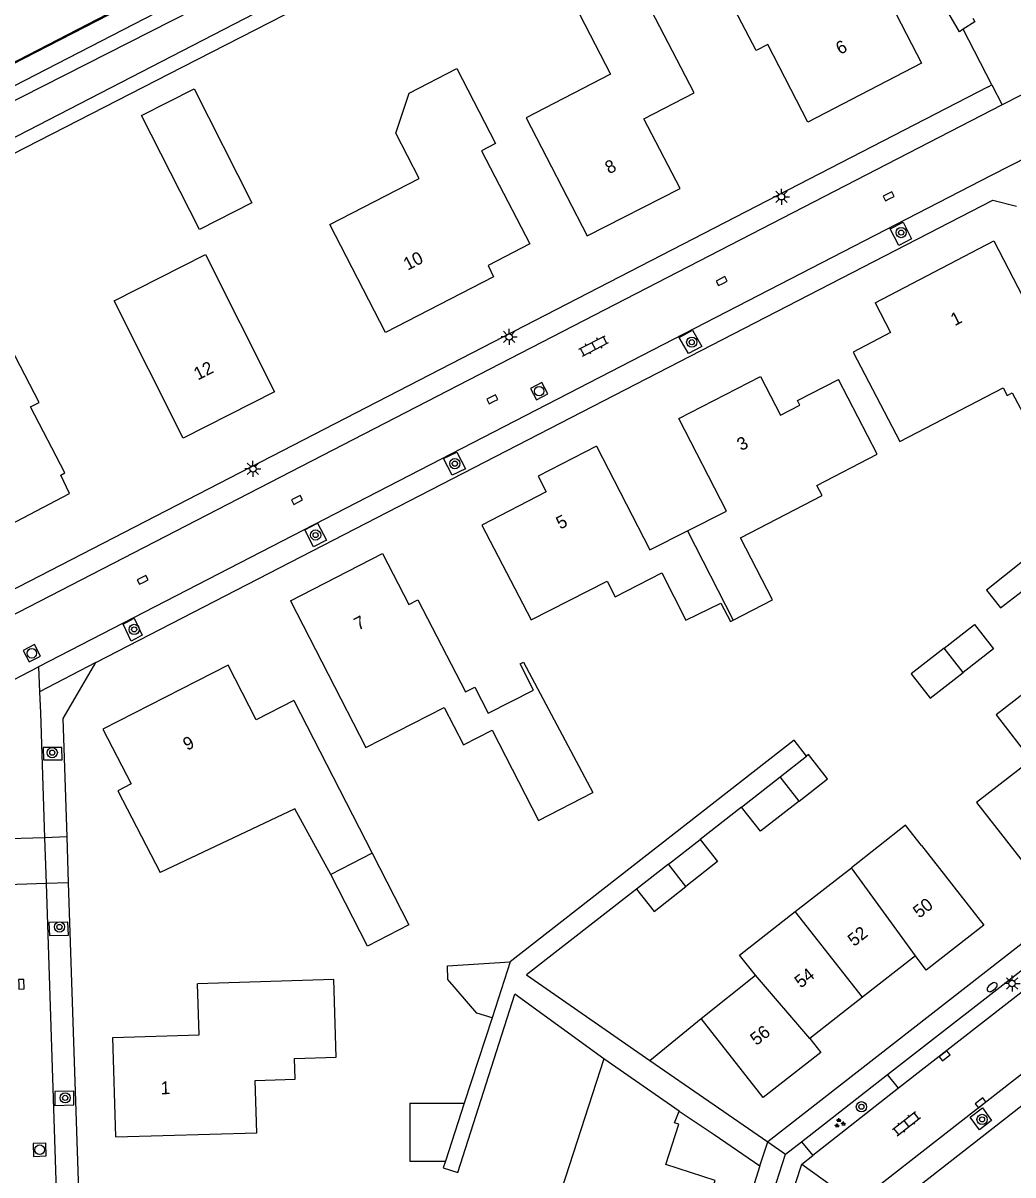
# Model space of a CAD drawing. Extents: x 136000 to 141014, y 402000 to 403500.
# Drawn here: x 137119.1 to 137196.5, y 402168.2 to 402258.2 of the extents above; entities that cross this region are included whole.
import ezdxf

# ---------------------------------------------------------------- set-up
doc = ezdxf.new("R2010")
doc.units = 0
for name, color, linetype in [('gg-afsc-erfafscheiding', 7, 'Continuous'), ('gg-anno-huisnummerreeks BGT', 7, 'Continuous'), ('gg-bbg-bijgebouw', 7, 'Continuous'), ('gg-bbg-gedigitaliseerde bebouwing', 7, 'Continuous'), ('gg-bbg-gedigitaliseerde bijgebouw', 7, 'Continuous'), ('gg-bbg-hoofdgebouw', 7, 'Continuous'), ('gg-bbg-luifel en loopbrug', 7, 'Continuous'), ('gg-bbg-tussenscheiding', 7, 'Continuous'), ('gg-knt-verharding', 7, 'Continuous'), ('gg-knt-verharding nz', 7, 'Continuous'), ('gg-kntw-bovenkant insteek waterloop', 7, 'Continuous'), ('gg-kntw-waterlijn', 7, 'Continuous'), ('gt-grn-groengrens', 7, 'Continuous'), ('gt-grn-weggrens', 7, 'Continuous'), ('gt-symb-boom', 7, 'Continuous'), ('gt-symb-brandkraan', 7, 'Continuous'), ('gt-symb-groenvak', 7, 'Continuous'), ('gt-symb-klinker verharding', 7, 'Continuous'), ('gt-symb-kolk', 7, 'Continuous'), ('gt-symb-lichtmast', 7, 'Continuous'), ('gt-symb-rioolschacht', 7, 'Continuous')]:
    doc.layers.add(name, color=color, linetype=linetype)

# ---------------------------------------------------------------- blocks, each defined once
blk = doc.blocks.new('gt0-KOLK')
at = {"layer": 'gt-symb-kolk'}
blk.add_lwpolyline([(0, 0), (0.375, 0), (0.375, 0.4), (-0.375, 0.4), (-0.375, 0), (0, 0)], dxfattribs=at)
blk = doc.blocks.new('gt0-GRVAK')
at = {"layer": 'gt-symb-groenvak'}
for p, q in [((-0.11, 0.189), (-0.228, 0.24)), ((-0.182, 0.153), (0.088, 0.153)), ((-0.091, 0.211), (-0.156, 0.322)), ((-0.047, 0.214), (-0.047, 0.393)), ((-0.004, 0.211), (0.061, 0.322)), ((0.015, 0.189), (0.133, 0.24)), ((0.262, -0.052), (0.197, 0.059)), ((0.305, -0.049), (0.305, 0.13)), ((0.349, -0.052), (0.414, 0.059)), ((-0.245, -0.228), (-0.363, -0.177)), ((-0.318, -0.264), (-0.047, -0.264)), ((-0.226, -0.206), (-0.291, -0.095)), ((-0.183, -0.203), (-0.183, -0.024)), ((-0.139, -0.206), (-0.074, -0.095)), ((-0.12, -0.228), (-0.002, -0.177)), ((0.243, -0.074), (0.125, -0.023)), ((0.17, -0.11), (0.441, -0.11)), ((0.368, -0.074), (0.486, -0.023))]:
    blk.add_line(p, q, dxfattribs=at)
blk = doc.blocks.new('gt0-BOOM')
at = {"layer": 'gt-symb-boom'}
for radius in [0.4, 0.2]:
    blk.add_circle((0, 0), radius, dxfattribs=at)
blk = doc.blocks.new('gt0-KL1')
at = {"layer": 'gt-symb-klinker verharding'}
for p, q in [((-1.15, 0.3), (1.15, 0.3)), ((-1, -0.3), (-1, 0.3)), ((-0.5, 0.3), (-0.5, 0.45)), ((0, -0.3), (0, 0.3)), ((0.5, 0.3), (0.5, 0.45)), ((1, -0.3), (1, 0.3)), ((-1.15, -0.3), (1.15, -0.3)), ((-0.5, -0.45), (-0.5, -0.3)), ((0.5, -0.45), (0.5, -0.3))]:
    blk.add_line(p, q, dxfattribs=at)
blk = doc.blocks.new('gt0-RS')
at = {"layer": 'gt-symb-rioolschacht'}
blk.add_lwpolyline([(-0.5, -0.5), (0.5, -0.5), (0.5, 0.5), (-0.5, 0.5)], close=True, dxfattribs=at)
blk.add_circle((0, 0), 0.375, dxfattribs=at)
blk = doc.blocks.new('gt0-LMAST')
at = {"layer": 'gt-symb-lichtmast'}
for p, q in [((-0.182, 0.173), (-0.447, 0.438)), ((-0.005, 0.246), (-0.005, 0.621)), ((0.172, 0.173), (0.437, 0.438)), ((-0.255, -0.004), (-0.63, -0.004)), ((-0.182, -0.181), (-0.447, -0.446)), ((-0.005, -0.254), (-0.005, -0.629)), ((0.437, -0.446), (0.172, -0.181)), ((0.245, -0.004), (0.62, -0.004))]:
    blk.add_line(p, q, dxfattribs=at)
blk.add_circle((-0.005, -0.004), 0.25, dxfattribs=at)
blk = doc.blocks.new('gt0-BR')
at = {"layer": 'gt-symb-brandkraan'}
for centre, radius, start, end in [((-0.244, 0), 0.206, 107.56694, 252.43307), ((0.599, -2.664), 3, 106.89205, 107.56694), ((0, -0.691), 0.938, 73.10799, 106.89205), ((-0.599, -2.664), 3, 72.43309, 73.10799), ((0.244, 0), 0.206, 287.56695, 72.43309), ((0.599, 2.664), 3, 252.43307, 253.10797), ((0, 0.691), 0.938, 253.10797, 286.89206), ((-0.599, 2.664), 3, 286.89206, 287.56695)]:
    blk.add_arc(centre, radius, start, end, dxfattribs=at)

msp = doc.modelspace()

# ---------------------------------------------------------------- linework, layer by layer
at = {"layer": 'gg-afsc-erfafscheiding'}
for p, q in [((137175.234, 402196.94), (137172.002, 402194.407)), ((137167.044, 402190.519), (137158.43, 402183.829)), ((137164.488, 402177.271), (137157.513, 402182.314)), ((137155.736, 402180.477), (137153.567, 402173.803)), ((137170.359, 402173.163), (137173.11, 402171.353))]:
    msp.add_line(p, q, dxfattribs=at)
for points in [[(137199.886, 402218.262), (137194.388, 402213.883), (137195.486, 402212.505), (137197.512, 402214.076)], [(137180.315, 402200.923), (137179.352, 402202.157), (137157.152, 402184.834)], [(137152.095, 402169.273), (137151.921, 402168.739), (137153.06, 402168.377), (137157.513, 402182.314)]]:
    msp.add_lwpolyline(points, dxfattribs=at)
at = {"layer": 'gg-bbg-bijgebouw'}
msp.add_lwpolyline([(137136.968, 402244.176), (137132.871, 402242.091), (137128.341, 402250.998), (137132.441, 402253.076), (137136.968, 402244.176)], dxfattribs=at)
at = {"layer": 'gg-bbg-gedigitaliseerde bebouwing'}
for p, q in [((137158.203, 402208.277), (137163.629, 402198.086)), ((137140.233, 402205.264), (137146.354, 402193.338)), ((137189.315, 402193.934), (137194.171, 402187.713)), ((137146.354, 402193.338), (137143.126, 402191.68)), ((137179.447, 402188.765), (137183.832, 402192.19)), ((137172.09, 402180.417), (137176.322, 402183.79)), ((137164.488, 402177.271), (137160.806, 402165.918))]:
    msp.add_line(p, q, dxfattribs=at)
for points in [[(137174.586, 402211.544), (137177.666, 402213.141), (137175.164, 402217.97), (137181.549, 402221.279), (137181.134, 402222.083), (137185.844, 402224.522), (137182.815, 402230.358)], [(137187.607, 402225.505), (137195.685, 402229.712), (137196.007, 402229.1), (137196.398, 402229.306), (137197.821, 402226.62), (137202.308, 402228.986)], [(137154.937, 402218.974), (137158.788, 402211.561), (137164.729, 402214.607), (137165.36, 402213.377), (137169.002, 402215.245)], [(137169.002, 402215.245), (137170.9, 402211.538), (137173.632, 402212.873)], [(137139.976, 402213.055), (137145.883, 402201.582), (137152.007, 402204.729), (137153.511, 402201.8), (137155.751, 402202.95), (137159.381, 402195.897), (137163.629, 402198.086)], [(137173.632, 402212.873), (137174.377, 402211.436), (137174.586, 402211.544)], [(137200.999, 402205.628), (137199.514, 402207.54), (137195.138, 402204.141), (137197.875, 402200.617)], [(137197.875, 402200.617), (137193.617, 402197.291), (137198.479, 402191.07)], [(137143.126, 402191.68), (137140.323, 402196.792), (137129.787, 402191.817)], [(137189.315, 402193.934), (137188.067, 402195.521), (137183.832, 402192.19)], [(137176.322, 402183.79), (137175.09, 402185.363), (137179.447, 402188.765)], [(137140.295, 402177.293), (137143.546, 402177.392), (137143.361, 402183.455), (137132.71, 402183.13)], [(137126.34, 402171.153), (137137.353, 402171.465), (137137.231, 402175.568), (137140.343, 402175.661), (137140.295, 402177.293)]]:
    msp.add_lwpolyline(points, dxfattribs=at)
at = {"layer": 'gg-bbg-gedigitaliseerde bijgebouw'}
for p, q in [((137178.25, 402199.304), (137180.315, 402200.923)), ((137175.234, 402196.94), (137178.25, 402199.304)), ((137169.523, 402192.463), (137172.002, 402194.407)), ((137169.523, 402192.463), (137167.044, 402190.519)), ((137149.3, 402173.803), (137153.567, 402173.803)), ((137153.567, 402173.803), (137152.095, 402169.273))]:
    msp.add_line(p, q, dxfattribs=at)
for points in [[(137191.077, 402209.359), (137193.448, 402211.2), (137194.928, 402209.296), (137192.557, 402207.454)], [(137191.077, 402209.359), (137188.507, 402207.362), (137189.986, 402205.458), (137192.557, 402207.454)], [(137179.736, 402197.408), (137181.953, 402199.146), (137180.467, 402201.042), (137180.315, 402200.923)], [(137179.736, 402197.408), (137176.721, 402195.044), (137175.234, 402196.94)], [(137172.002, 402194.407), (137173.359, 402192.675), (137170.88, 402190.732)], [(137167.044, 402190.519), (137168.401, 402188.788), (137170.88, 402190.732)], [(137149.3, 402173.803), (137149.3, 402169.273), (137152.095, 402169.273)]]:
    msp.add_lwpolyline(points, dxfattribs=at)
at = {"layer": 'gg-bbg-hoofdgebouw'}
for p, q in [((137188.829, 402185.307), (137184.696, 402182.069)), ((137184.696, 402182.069), (137180.57, 402178.837)), ((137176.941, 402174.233), (137172.09, 402180.417)), ((137170.359, 402173.163), (137164.488, 402177.271))]:
    msp.add_line(p, q, dxfattribs=at)
for points in [[(137189.655, 402262.053), (137186.547, 402260.445), (137189.322, 402255.08), (137180.42, 402250.476), (137177.297, 402256.539), (137176.374, 402256.075), (137174.442, 402259.81), (137178.182, 402261.759), (137178.665, 402260.826)], [(137163.17, 402241.585), (137170.433, 402245.286), (137167.607, 402250.721), (137171.543, 402252.763), (137167.168, 402261.215), (137162.607, 402258.856), (137165.001, 402254.226), (137158.406, 402250.817), (137163.17, 402241.585)], [(137147.417, 402234.028), (137143.058, 402242.473), (137150.05, 402246.079), (137148.226, 402249.614), (137149.257, 402252.747), (137152.988, 402254.662), (137156, 402248.794), (137154.923, 402248.24), (137158.703, 402240.958), (137155.424, 402239.257), (137155.865, 402238.386), (137147.417, 402234.028)], [(137185.68, 402236.339), (137194.96, 402241.184), (137198.35, 402234.646), (137199.151, 402235.051), (137202.308, 402228.986)], [(137138.729, 402229.381), (137131.591, 402225.774), (137126.187, 402236.504), (137133.332, 402240.117), (137138.729, 402229.381)], [(137110.555, 402216.953), (137113.619, 402218.514), (137113.894, 402217.965), (137114.839, 402218.482), (137114.601, 402219.035), (137116.234, 402219.865), (137116.975, 402218.457), (137122.707, 402221.442), (137122.022, 402222.876), (137122.345, 402223.064), (137119.662, 402228.217), (137120.324, 402228.557), (137115.128, 402238.562), (137108.516, 402235.127), (137111.46, 402229.516), (137110.614, 402226.66), (137106.597, 402224.573), (137110.555, 402216.953)], [(137185.68, 402236.339), (137186.89, 402234.031), (137183.963, 402232.496), (137187.607, 402225.505)], [(137170.345, 402227.301), (137176.731, 402230.6), (137178.296, 402227.571), (137179.806, 402228.351), (137179.629, 402228.704), (137182.815, 402230.358)], [(137171.013, 402218.53), (137174.075, 402220.064), (137170.345, 402227.301)], [(137163.912, 402225.143), (137159.352, 402222.794), (137159.962, 402221.585), (137154.937, 402218.974)], [(137163.912, 402225.143), (137168.075, 402217.057), (137171.013, 402218.53)], [(137139.976, 402213.055), (137147.172, 402216.762), (137149.229, 402212.771), (137149.94, 402213.137)], [(137149.94, 402213.137), (137153.658, 402205.94), (137154.385, 402206.313), (137155.431, 402204.276), (137158.97, 402206.085), (137157.925, 402208.129), (137158.203, 402208.277)], [(137140.233, 402205.264), (137137.286, 402203.756), (137135.109, 402208.023), (137125.321, 402203.015), (137127.523, 402198.752), (137126.488, 402198.21), (137129.787, 402191.817)], [(137194.171, 402187.713), (137189.683, 402184.183), (137188.829, 402185.307)], [(137126.34, 402171.153), (137126.096, 402178.922), (137132.835, 402179.134), (137132.71, 402183.13)], [(137180.57, 402178.837), (137181.436, 402177.746), (137176.941, 402174.233)], [(137169.337, 402169.007), (137170.351, 402172.153), (137169.999, 402172.266), (137170.359, 402173.163)], [(137171.466, 402162.46), (137173.184, 402167.76), (137169.337, 402169.007)]]:
    msp.add_lwpolyline(points, dxfattribs=at)
at = {"layer": 'gg-bbg-luifel en loopbrug'}
msp.add_line((137157.152, 402184.834), (137155.736, 402180.477), dxfattribs=at)
for points in [[(137146.354, 402193.338), (137149.234, 402187.727), (137146.006, 402186.07), (137143.126, 402191.68)], [(137155.736, 402180.477), (137154.541, 402180.819), (137152.274, 402183.462), (137152.247, 402184.541), (137157.152, 402184.834)]]:
    msp.add_lwpolyline(points, dxfattribs=at)
at = {"layer": 'gg-bbg-tussenscheiding'}
for p, q in [((137171.013, 402218.53), (137174.586, 402211.544)), ((137192.557, 402207.454), (137191.077, 402209.359)), ((137179.736, 402197.408), (137178.25, 402199.304)), ((137170.88, 402190.732), (137169.523, 402192.463)), ((137188.829, 402185.307), (137183.832, 402192.19)), ((137184.696, 402182.069), (137179.447, 402188.765)), ((137180.57, 402178.837), (137176.322, 402183.79))]:
    msp.add_line(p, q, dxfattribs=at)
at = {"layer": 'gg-knt-verharding'}
for p, q in [((137192.27, 402257.54), (137189.655, 402262.053)), ((137194.817, 402253.388), (137192.576, 402257.734)), ((137194.511, 402253.23), (137112.718, 402211.057)), ((137194.511, 402253.23), (137194.817, 402253.388)), ((137219.657, 402203.828), (137177.285, 402170.761)), ((137186.663, 402176.03), (137216.386, 402199.194)), ((137120.761, 402194.542), (137116.255, 402194.394)), ((137122.515, 402194.6), (137120.761, 402194.542)), ((137122.633, 402191.022), (137122.515, 402194.6)), ((137120.879, 402190.964), (137116.373, 402190.816)), ((137122.633, 402191.022), (137120.879, 402190.964)), ((137124.321, 402139.859), (137122.633, 402191.022)), ((137158.43, 402183.829), (137168.078, 402177.141)), ((137168.078, 402177.141), (137172.09, 402180.417)), ((137168.078, 402177.141), (137177.285, 402170.761)), ((137179.917, 402170.782), (137186.663, 402176.03)), ((137187.506, 402174.961), (137186.663, 402176.03)), ((137187.506, 402174.961), (137180.809, 402169.696)), ((137173.11, 402171.353), (137176.678, 402168.885)), ((137178.678, 402169.818), (137179.917, 402170.782)), ((137179.917, 402170.782), (137180.809, 402169.696)), ((137173.776, 402154.537), (137178.678, 402169.818)), ((137176.678, 402168.885), (137161.685, 402122.523))]:
    msp.add_line(p, q, dxfattribs=at)
for points in [[(137114.039, 402252.931), (137136.533, 402264.565), (137178.437, 402286.603), (137198.547, 402296.864)], [(137193.315, 402258.609), (137193.487, 402258.314), (137192.576, 402257.734)], [(137124.757, 402208.239), (137194.898, 402244.385), (137196.728, 402243.905)], [(137186.868, 402242.141), (137187.865, 402242.657), (137188.526, 402241.349), (137187.529, 402240.833), (137186.868, 402242.141)], [(137170.376, 402233.651), (137171.405, 402234.204), (137172.129, 402232.934), (137171.1, 402232.381), (137170.376, 402233.651)], [(137151.944, 402224.19), (137152.974, 402224.684), (137153.659, 402223.366), (137152.63, 402222.872), (137151.944, 402224.19)], [(137141.098, 402218.601), (137142.102, 402219.12), (137142.789, 402217.797), (137141.785, 402217.278), (137141.098, 402218.601)], [(137126.905, 402211.228), (137127.773, 402211.691), (137128.388, 402210.367), (137127.52, 402209.904), (137126.905, 402211.228)], [(137122.515, 402194.6), (137122.209, 402203.872), (137124.757, 402208.239)], [(137120.635, 402201.587), (137120.665, 402200.62), (137122.131, 402200.636), (137122.101, 402201.603), (137120.635, 402201.587)], [(137218.597, 402190.349), (137189.049, 402167.254), (137186.912, 402164.258)], [(137121.082, 402187.911), (137121.13, 402186.888), (137122.628, 402186.924), (137122.579, 402187.947), (137121.082, 402187.911)], [(137121.553, 402174.709), (137121.563, 402173.625), (137123.045, 402173.654), (137123.035, 402174.738), (137121.553, 402174.709)], [(137193.125, 402172.714), (137194.072, 402173.437), (137194.792, 402172.432), (137193.845, 402171.708), (137193.125, 402172.714)]]:
    msp.add_lwpolyline(points, dxfattribs=at)
at = {"layer": 'gg-knt-verharding nz'}
for p, q in [((137199.183, 402253.649), (137195.628, 402251.816)), ((137195.628, 402251.816), (137113.624, 402209.527)), ((137120.282, 402207.889), (137120.367, 402205.951)), ((137217.227, 402198.134), (137187.506, 402174.961)), ((137225.226, 402198.005), (137184.223, 402165.979)), ((137120.761, 402194.542), (137120.879, 402190.964)), ((137120.879, 402190.964), (137122.81, 402132.398)), ((137179.953, 402169.024), (137180.809, 402169.696)), ((137175.077, 402154.14), (137179.953, 402169.024))]:
    msp.add_line(p, q, dxfattribs=at)
for points in [[(137197.733, 402247.823), (137194.744, 402246.314), (137120.282, 402207.889)], [(137120.367, 402205.951), (137120.439, 402204.3), (137120.761, 402194.542)]]:
    msp.add_lwpolyline(points, dxfattribs=at)
at = {"layer": 'gg-kntw-bovenkant insteek waterloop'}
msp.add_line((137046.682, 402212.26), (137179.816, 402280.985), dxfattribs=at)
msp.add_lwpolyline([(137044.528, 402217.609), (137110.163, 402251.03), (137112.495, 402252.06), (137194.09, 402293.977)], dxfattribs=at)
at = {"layer": 'gg-kntw-waterlijn'}
msp.add_lwpolyline([(137043.484, 402206.955), (137042.996, 402210.257), (137043.425, 402211.894), (137044.284, 402213.469), (137046.308, 402215.065), (137065.655, 402225.358), (137078.207, 402231.684), (137102.163, 402243.942), (137139.102, 402262.696), (137173.81, 402280.459), (137194.975, 402291.136), (137194.445, 402292.358), (137162.599, 402276.104), (137107.252, 402247.583), (137063.182, 402225.333), (137045.277, 402215.852), (137043.437, 402214.4), (137042.367, 402212.642), (137041.807, 402211.297), (137041.833, 402208.678), (137041.99, 402206.763)], dxfattribs=at)
at = {"layer": 'gt-grn-groengrens'}
msp.add_line((137192.576, 402257.734), (137192.27, 402257.54), dxfattribs=at)
msp.add_lwpolyline([(137049.629, 402172.09), (137049.013, 402172.486), (137046.817, 402196.934), (137045.881, 402208.692), (137046.778, 402211.327), (137131.556, 402254.798), (137164.49, 402271.663), (137180.412, 402279.845)], dxfattribs=at)
at = {"layer": 'gt-grn-weggrens'}
for p, q in [((137194.817, 402253.388), (137195.628, 402251.816)), ((137124.757, 402208.239), (137120.367, 402205.951)), ((137112.958, 402204.103), (137120.282, 402207.889)), ((137176.678, 402168.885), (137177.285, 402170.761)), ((137177.285, 402170.761), (137178.678, 402169.818)), ((137179.953, 402169.024), (137184.223, 402165.979))]:
    msp.add_line(p, q, dxfattribs=at)

# ---------------------------------------------------------------- block references
at = {"layer": 'gt-symb-boom'}
for p in [(137187.722, 402241.839), (137171.349, 402233.272), (137152.832, 402223.78), (137141.947, 402218.2), (137127.76, 402210.825), (137121.357, 402201.191), (137121.922, 402187.566), (137122.37, 402174.21), (137184.613, 402173.514), (137194.047, 402172.525)]:
    msp.add_blockref('gt0-BOOM', p, dxfattribs=at)
at = {"layer": 'gt-symb-brandkraan', "rotation": 38.17653760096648}
msp.add_blockref('gt0-BR', (137194.831, 402182.863), dxfattribs=at)
at = {"layer": 'gt-symb-groenvak'}
msp.add_blockref('gt0-GRVAK', (137182.906, 402172.223), dxfattribs=at)
at = {"layer": 'gt-symb-klinker verharding'}
for p, rotation in [((137163.687, 402232.984), 27.307780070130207), ((137188.131, 402172.197), 38.01566048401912)]:
    msp.add_blockref('gt0-KL1', p, dxfattribs=dict(at, rotation=rotation))
at = {"layer": 'gt-symb-kolk'}
for p, rotation in [((137186.84, 402244.5), 27.256871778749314), ((137173.78, 402237.871), 27.256871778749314), ((137155.849, 402228.625), 27.256871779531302), ((137140.582, 402220.772), 27.256871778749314), ((137128.523, 402214.522), 27.256871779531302), ((137118.741, 402183.085), -88.22439947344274), ((137191.245, 402177.337), 38.01566048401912), ((137194.055, 402173.66), 38.01566048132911)]:
    msp.add_blockref('gt0-KOLK', p, dxfattribs=dict(at, rotation=rotation))
at = {"layer": 'gt-symb-lichtmast'}
for p in [(137178.365, 402244.644), (137157.082, 402233.686), (137137.055, 402223.373), (137196.392, 402183.154)]:
    msp.add_blockref('gt0-LMAST', p, dxfattribs=at)
at = {"layer": 'gt-symb-rioolschacht'}
for p, rotation in [((137159.422, 402229.443), 27.256871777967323), ((137119.76, 402208.961), 27.256871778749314), ((137120.373, 402170.155), -88.22439947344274)]:
    msp.add_blockref('gt0-RS', p, dxfattribs=dict(at, rotation=rotation))

# ---------------------------------------------------------------- texts
at = {"layer": 'gg-anno-huisnummerreeks BGT'}
for s, rotation, p in [('6', 27.3, (137182.939, 402255.719)), ('8', 27, (137164.887, 402246.388)), ('10', 27.3, (137149.136, 402238.853)), ('1', 27.6, (137191.912, 402234.516)), ('12', 26.8, (137132.738, 402230.276)), ('3', 27.3, (137175.207, 402224.748)), ('5', 27.3, (137161.069, 402218.617)), ('7', 27.3, (137145.274, 402210.722)), ('9', 27.1, (137131.899, 402201.326)), ('50', 38.2, (137189.138, 402188.208)), ('52', 38.1, (137184.033, 402185.996)), ('54', 38.1, (137179.878, 402182.742)), ('56', 38, (137176.408, 402178.258)), ('1', 1.8, (137129.848, 402174.485))]:
    msp.add_text(s, height=1, rotation=rotation, dxfattribs=at).set_placement(p)

doc.saveas('drawing.dxf')
